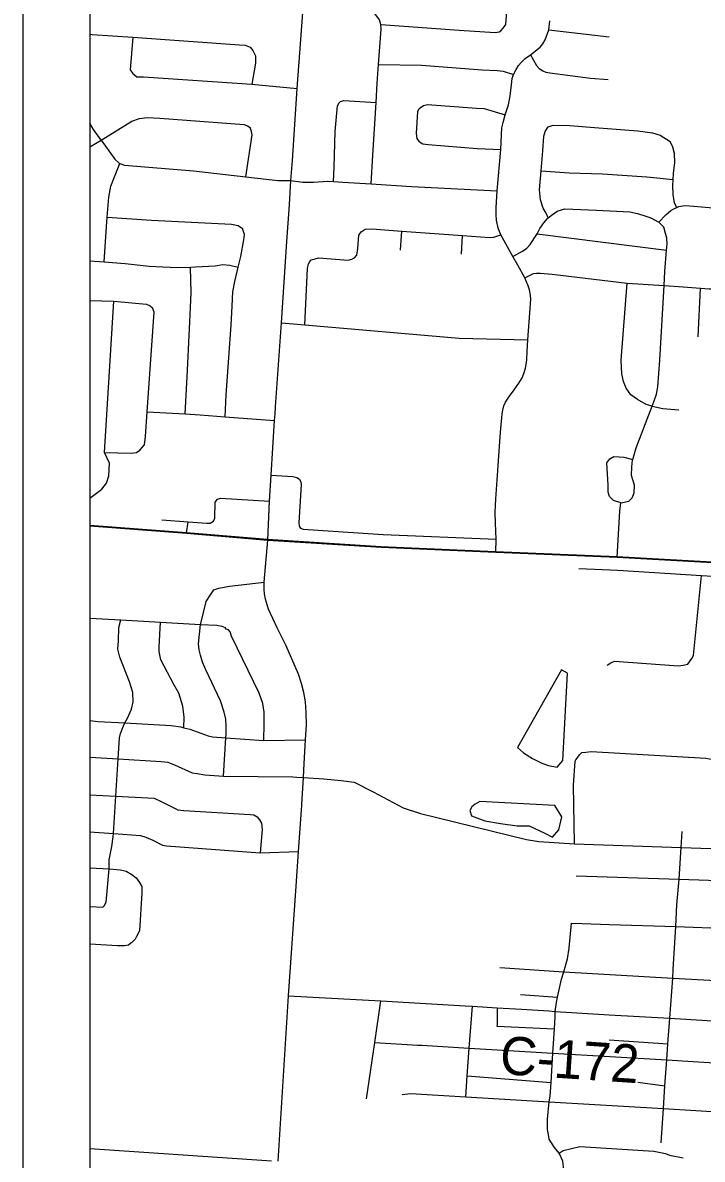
# Model space of a CAD drawing. Extents: x 0 to 34, y 0 to 22.
# Drawn here: x 2 to 3.011, y 15.572 to 17.262 of the extents above; entities that cross this region are included whole.
import ezdxf

# ---------------------------------------------------------------- set-up
doc = ezdxf.new("R2010")
doc.units = 0
for name, color, linetype in [('GM_X_City_Street', 7, 'Continuous'), ('GM_X_Corporation', 7, 'Continuous'), ('GM_X_County_Road', 7, 'Continuous'), ('GM_X_County_Road_Text', 7, 'Continuous'), ('GM_X_Minor_Lake', 7, 'Continuous'), ('GM_X_Township_Road', 7, 'Continuous'), ('SH_Data', 7, 'Continuous')]:
    doc.layers.add(name, color=color, linetype=linetype)

msp = doc.modelspace()

# ---------------------------------------------------------------- linework, layer by layer
at = {"layer": 'GM_X_City_Street'}
for p, q in [((2.7828, 17.2515), (2.8725, 17.2408)), ((2.5622, 16.9236), (2.5639, 16.9521)), ((2.6529, 16.9176), (2.6544, 16.9455)), ((2.7655, 16.9481), (2.9578, 16.9236)), ((3.0049, 16.795), (3.0084, 16.8673)), ((2.2071, 16.5224), (2.2462, 16.5198))]:
    msp.add_line(p, q, dxfattribs=at)
for points in [[(2.3754, 16.6801), (2.3762, 16.6907), (2.3851, 16.8158), (2.393, 16.9367), (2.3967, 16.9913), (2.3987, 17.0273), (2.4012, 17.0569), (2.4084, 17.1642), (2.416, 17.2704), (2.4254, 17.4108), (2.4323, 17.5151), (2.4397, 17.6214), (2.4448, 17.7051), (2.4589, 17.9206), (2.4607, 17.957), (2.4706, 18.1283), (2.4796, 18.2726), (2.4824, 18.3215)], [(2.7114, 17.2497), (2.7145, 17.2538), (2.7189, 17.2593), (2.7221, 17.3047), (2.7236, 17.3198), (2.724, 17.3301), (2.7255, 17.3353), (2.7272, 17.3394), (2.7299, 17.344), (2.7349, 17.349), (2.7398, 17.3524), (2.7463, 17.3546), (2.7525, 17.3548), (2.7901, 17.3519)], [(2.5183, 17.0222), (2.5209, 17.0652), (2.5257, 17.1435), (2.5274, 17.1719), (2.5294, 17.1998), (2.5332, 17.2524), (2.5329, 17.2593), (2.5307, 17.2662), (2.5208, 17.2798)], [(2.5329, 17.2593), (2.6491, 17.251), (2.7027, 17.2476), (2.7087, 17.2482), (2.7114, 17.2497)], [(2.7036, 16.4747), (2.7044, 16.4939), (2.7034, 16.5177), (2.703, 16.5338), (2.7037, 16.5537), (2.7057, 16.5816), (2.7087, 16.625), (2.7109, 16.6528), (2.7128, 16.6742), (2.7132, 16.6804), (2.7141, 16.6856), (2.7156, 16.692), (2.7184, 16.6975), (2.7242, 16.7068), (2.731, 16.7161), (2.7381, 16.7259), (2.7428, 16.7339), (2.7454, 16.7403), (2.748, 16.7483), (2.7493, 16.7566), (2.7498, 16.7613), (2.7505, 16.7728), (2.7514, 16.7902), (2.755, 16.8368), (2.7556, 16.8448), (2.7557, 16.8502), (2.7555, 16.8568), (2.754, 16.8649), (2.7519, 16.8708), (2.7471, 16.8824), (2.7365, 16.9013), (2.7293, 16.9141), (2.7112, 16.9465), (2.7071, 16.9562), (2.7048, 16.9681), (2.7042, 16.9763), (2.7045, 16.9868), (2.7057, 17.012), (2.7111, 17.0733), (2.7127, 17.1056), (2.7145, 17.1134), (2.7179, 17.1252), (2.7227, 17.1398), (2.7253, 17.153), (2.7271, 17.1694), (2.7283, 17.179), (2.7299, 17.185), (2.7339, 17.1924), (2.7377, 17.1982), (2.7417, 17.203), (2.7475, 17.2088), (2.7552, 17.2141), (2.77, 17.2254), (2.7737, 17.2304), (2.777, 17.2365), (2.7828, 17.2515), (2.7842, 17.2647)], [(2.1, 17.2448), (2.1032, 17.2446), (2.1638, 17.2404), (2.3227, 17.2292), (2.331, 17.2288), (2.3382, 17.2258), (2.3424, 17.2208), (2.3462, 17.2128), (2.3461, 17.2018), (2.341, 17.1708)], [(2.1638, 17.2404), (2.16, 17.1919), (2.1635, 17.1869), (2.1699, 17.1816), (2.1798, 17.1816), (2.341, 17.1708), (2.4084, 17.1642)], [(2.7552, 17.2141), (2.7642, 17.1983), (2.7682, 17.194), (2.7735, 17.1904), (2.7784, 17.1883), (2.7843, 17.1873), (2.8446, 17.1796), (2.8708, 17.1773)], [(2.5294, 17.1998), (2.5934, 17.1988), (2.6835, 17.1918), (2.7057, 17.1908), (2.7145, 17.19), (2.7299, 17.185)], [(2.4621, 17.0258), (2.4633, 17.0471), (2.4648, 17.1003), (2.4684, 17.1382), (2.4708, 17.1428), (2.4727, 17.145)], [(2.4727, 17.145), (2.4777, 17.1465), (2.4856, 17.146), (2.5257, 17.1435)], [(2.5898, 17.1346), (2.5962, 17.139), (2.6024, 17.1402), (2.6749, 17.135), (2.6867, 17.1342), (2.7179, 17.1252)], [(2.5904, 17.0846), (2.5868, 17.0898), (2.5856, 17.0972), (2.588, 17.1298), (2.5898, 17.1346)], [(2.1, 17.0775), (2.1168, 17.0874), (2.1625, 17.1155), (2.1739, 17.1193), (2.1853, 17.1212), (2.2042, 17.1199), (2.3295, 17.1104), (2.3344, 17.1084), (2.3386, 17.1062)], [(2.1168, 17.0874), (2.1051, 17.1032), (2.1, 17.1128)], [(2.3318, 17.0328), (2.3412, 17.0951), (2.3401, 17.1001), (2.3386, 17.1062)], [(2.7806, 17.1058), (2.7818, 17.1073), (2.789, 17.1095), (2.8137, 17.1092), (2.8505, 17.1061), (2.9151, 17.1012), (2.9371, 17.098), (2.9485, 17.0948), (2.9632, 17.0851)], [(2.7818, 16.9718), (2.7789, 16.9785), (2.7744, 16.9861), (2.7703, 16.9987), (2.769, 17.0132), (2.7713, 17.0417), (2.7738, 17.0716), (2.7751, 17.0933), (2.7771, 17.1001), (2.7806, 17.1058)], [(2.1168, 17.0874), (2.1369, 17.0589), (2.1433, 17.0531), (2.1444, 17.0527), (2.1512, 17.05), (2.2541, 17.0415), (2.3318, 17.0328), (2.3797, 17.0275)], [(2.5904, 17.0846), (2.5954, 17.0816), (2.6034, 17.0806), (2.6762, 17.075), (2.7111, 17.0733)], [(2.973, 16.9869), (2.9698, 16.9934), (2.9677, 17.0064), (2.9671, 17.0197), (2.9675, 17.0287), (2.968, 17.0379), (2.9701, 17.0539), (2.9695, 17.0676), (2.9669, 17.0767), (2.9632, 17.0851)], [(2.1214, 16.9062), (2.1247, 16.9585), (2.1258, 16.973), (2.1279, 17.0025), (2.131, 17.0188), (2.1375, 17.0351), (2.1444, 17.0527)], [(2.7713, 17.0417), (2.8129, 17.0385), (2.8623, 17.0372), (2.9284, 17.033), (2.9675, 17.0287)], [(2.3797, 17.0275), (2.3837, 17.0272), (2.3987, 17.0273), (2.4166, 17.025), (2.4325, 17.0247), (2.4538, 17.0263), (2.4621, 17.0258), (2.4762, 17.0248), (2.5183, 17.0222), (2.5784, 17.0183), (2.7057, 17.012)], [(2.9463, 16.9652), (2.9567, 16.9761), (2.9644, 16.9825), (2.9697, 16.9855), (2.973, 16.9869), (2.9762, 16.9884), (2.985, 16.9899), (2.9986, 16.9889), (3.0211, 16.9872), (3.0845, 16.9822), (3.1057, 16.9805), (3.1133, 16.9808), (3.1154, 16.9816), (3.1191, 16.983), (3.1286, 16.989), (3.1425, 17.0022), (3.1711, 17.0347)], [(2.1258, 16.973), (2.1916, 16.9685), (2.3108, 16.9623), (2.3203, 16.9604), (2.3267, 16.9558)], [(2.7293, 16.9141), (2.7437, 16.9222), (2.7497, 16.9265), (2.755, 16.9322), (2.7655, 16.9481), (2.7695, 16.9561), (2.7753, 16.9641), (2.7807, 16.9708), (2.7818, 16.9718), (2.788, 16.9768), (2.7952, 16.9817), (2.8063, 16.985), (2.8534, 16.9833), (2.9032, 16.9805), (2.9145, 16.9781), (2.9255, 16.9749), (2.9346, 16.9718), (2.9463, 16.9652)], [(2.3011, 16.6758), (2.3028, 16.7083), (2.3099, 16.812), (2.3115, 16.8404), (2.3127, 16.8617), (2.3155, 16.8773), (2.3205, 16.8982), (2.3243, 16.9144), (2.3289, 16.9391), (2.3297, 16.9471), (2.3267, 16.9558)], [(2.4289, 16.9092), (2.435, 16.911), (2.44, 16.9125), (2.484, 16.9088), (2.4898, 16.9102), (2.4936, 16.9124), (2.4971, 16.9162), (2.4987, 16.926), (2.4998, 16.9462), (2.5033, 16.951), (2.5094, 16.9548), (2.5193, 16.9554), (2.5639, 16.9521), (2.6544, 16.9455), (2.6946, 16.9426), (2.7008, 16.9431), (2.7112, 16.9465)], [(2.8842, 16.467), (2.8881, 16.5354), (2.89, 16.5477), (2.9015, 16.5503), (2.9067, 16.5552), (2.9094, 16.5626), (2.91, 16.5741), (2.9054, 16.5886), (2.9063, 16.6015), (2.9072, 16.6114), (2.9076, 16.6126), (2.9127, 16.6295), (2.9363, 16.6916), (2.9393, 16.6996), (2.9428, 16.7094), (2.9448, 16.7204), (2.9479, 16.7603), (2.9542, 16.8712), (2.9554, 16.8921), (2.9578, 16.9236), (2.9585, 16.9327), (2.9582, 16.9422), (2.9564, 16.9487), (2.9535, 16.9579), (2.9463, 16.9652)], [(2.1, 16.908), (2.1214, 16.9062), (2.1523, 16.9037), (2.188, 16.9001), (2.2085, 16.8989), (2.2301, 16.8977), (2.2498, 16.8985), (2.2571, 16.8987), (2.2863, 16.9005), (2.2977, 16.9024), (2.3083, 16.9016), (2.3205, 16.8982)], [(2.4198, 16.8127), (2.4238, 16.8964), (2.425, 16.9036), (2.427, 16.9066), (2.4289, 16.9092)], [(2.2415, 16.6802), (2.2448, 16.7355), (2.248, 16.8069), (2.2505, 16.86), (2.2498, 16.8985)], [(2.7471, 16.8824), (2.7557, 16.8872), (2.7599, 16.8889), (2.7642, 16.8895), (2.77, 16.8893), (2.7875, 16.8881), (2.899, 16.8748), (2.9542, 16.8712), (2.9825, 16.8694), (3.0084, 16.8673), (3.0213, 16.8663), (3.0277, 16.8662), (3.0395, 16.868), (3.0586, 16.8727), (3.0666, 16.873), (3.0784, 16.8733), (3.1178, 16.8704), (3.1711, 16.8665)], [(2.9363, 16.6916), (2.9275, 16.6944), (2.9146, 16.7014), (2.9048, 16.7083), (2.8977, 16.7183), (2.8936, 16.7282), (2.8915, 16.7396), (2.8902, 16.7602), (2.899, 16.8748)], [(2.1, 16.8487), (2.1356, 16.848), (2.184, 16.8432), (2.1897, 16.8409), (2.1931, 16.8378)], [(2.1, 16.5547), (2.1175, 16.568), (2.1246, 16.5773), (2.1283, 16.5883), (2.1293, 16.6071), (2.1218, 16.6229), (2.1356, 16.848)], [(2.1218, 16.6229), (2.1612, 16.6219), (2.1692, 16.6226), (2.1742, 16.6264), (2.181, 16.6343), (2.1826, 16.6465), (2.1852, 16.6835), (2.1957, 16.8317), (2.1931, 16.8378)], [(2.3851, 16.8158), (2.4198, 16.8127), (2.6492, 16.793), (2.7514, 16.7902)], [(2.1852, 16.6835), (2.2415, 16.6802), (2.2639, 16.6788), (2.3011, 16.6758), (2.3747, 16.6703)], [(2.9363, 16.6916), (2.9525, 16.688), (2.976, 16.6862)], [(2.3644, 16.4926), (2.3672, 16.5502), (2.3696, 16.589), (2.3747, 16.6703), (2.3754, 16.6801)], [(2.89, 16.5477), (2.8791, 16.5514), (2.8731, 16.5572), (2.8711, 16.564), (2.8711, 16.5743), (2.8691, 16.6076), (2.8734, 16.6133), (2.8795, 16.617), (2.8875, 16.6165), (2.8943, 16.6157), (2.9076, 16.6126)], [(2.3696, 16.589), (2.402, 16.5872), (2.4078, 16.5857), (2.4117, 16.5832), (2.4138, 16.5789), (2.4142, 16.5752), (2.4106, 16.5184), (2.4114, 16.513), (2.4133, 16.5101), (2.4173, 16.5086), (2.5362, 16.5008), (2.7044, 16.4939)], [(2.2437, 16.5027), (2.2462, 16.5198), (2.2738, 16.5177), (2.2786, 16.5179), (2.2836, 16.5206), (2.2857, 16.5251), (2.2865, 16.5491), (2.2899, 16.5535), (2.2941, 16.5551), (2.3672, 16.5502)], [(2.4151, 16.0995), (2.4176, 16.1392), (2.4189, 16.1602), (2.4207, 16.1954), (2.422, 16.2177), (2.4219, 16.2362), (2.4206, 16.2521), (2.4181, 16.2658), (2.4149, 16.279), (2.4104, 16.2929), (2.3917, 16.3353), (2.3787, 16.3619), (2.3657, 16.3897), (2.3612, 16.4045), (2.3596, 16.4127), (2.3591, 16.4196), (2.3594, 16.4297), (2.3644, 16.4926)], [(2.8272, 16.4501), (2.8851, 16.4478), (3.0099, 16.44), (3.0775, 16.4361), (3.1074, 16.4346), (3.1381, 16.433), (3.1874, 16.4301), (3.2697, 16.4245), (3.406, 16.4147), (3.4454, 16.4112)], [(2.2989, 16.1413), (2.3022, 16.1984), (2.3026, 16.2039), (2.3028, 16.2161), (2.3023, 16.226), (2.2996, 16.2366), (2.2944, 16.2532), (2.2723, 16.2996), (2.2673, 16.311), (2.2645, 16.3216), (2.2626, 16.3291), (2.2613, 16.3382), (2.2646, 16.3672), (2.2648, 16.3687), (2.2728, 16.401), (2.2791, 16.4109), (2.2843, 16.4186), (2.2919, 16.421), (2.3077, 16.4238), (2.3594, 16.4297)], [(2.9894, 16.308), (2.9952, 16.3166), (2.998, 16.3211), (3.0099, 16.44)], [(2.1, 16.3764), (2.1458, 16.3739), (2.2048, 16.3706), (2.2646, 16.3672), (2.2887, 16.3659), (2.2963, 16.3644), (2.3012, 16.3626)], [(2.1286, 16.0035), (2.1285, 16.0168), (2.1328, 16.0369), (2.1345, 16.051), (2.1349, 16.0561), (2.1384, 16.1116), (2.1419, 16.1671), (2.1439, 16.1984), (2.1453, 16.2049), (2.1498, 16.2163), (2.1521, 16.2205), (2.1561, 16.2277), (2.162, 16.2411), (2.1641, 16.2518), (2.1636, 16.2658), (2.1589, 16.2817), (2.1445, 16.3183), (2.1417, 16.3301), (2.1427, 16.3426), (2.1432, 16.3624), (2.1458, 16.3739)], [(2.2397, 16.2135), (2.2402, 16.2294), (2.2381, 16.2454), (2.2322, 16.2647), (2.2249, 16.2779), (2.2055, 16.3145), (2.2031, 16.3266), (2.203, 16.3338), (2.2048, 16.3706)], [(2.3588, 16.1943), (2.3592, 16.2194), (2.359, 16.2365), (2.357, 16.2493), (2.3519, 16.2648), (2.3108, 16.3498), (2.3085, 16.3562), (2.3062, 16.3592), (2.3027, 16.36), (2.3012, 16.3626)], [(2.8692, 16.3064), (2.8749, 16.3101), (2.8803, 16.3126), (2.9757, 16.3057), (2.9825, 16.3063), (2.9894, 16.308)], [(2.1, 16.2243), (2.1118, 16.2227), (2.1521, 16.2205), (2.2206, 16.2167), (2.235, 16.2146), (2.2397, 16.2135), (2.2487, 16.2113), (2.265, 16.2054), (2.2757, 16.2014), (2.2822, 16.1999), (2.3022, 16.1984), (2.3588, 16.1943), (2.4207, 16.1954)], [(2.8281, 16.1733), (2.8316, 16.1766), (2.8376, 16.1773), (2.8456, 16.1779), (3.0163, 16.1681), (3.0273, 16.1664), (3.039, 16.1635), (3.0594, 16.1638), (3.0724, 16.1673), (3.0877, 16.175), (3.0985, 16.1842), (3.1077, 16.1901), (3.1233, 16.1913), (3.1419, 16.1912), (3.1426, 16.1912), (3.1446, 16.1911), (3.1515, 16.1907)], [(2.1, 16.1695), (2.1419, 16.1671), (2.206, 16.1634), (2.2158, 16.1621), (2.2256, 16.1584), (2.2522, 16.1465), (2.2594, 16.1456), (2.2711, 16.1434), (2.2989, 16.1413), (2.402, 16.1403), (2.4079, 16.1399)], [(2.8209, 16.0408), (2.8192, 16.1279), (2.8218, 16.1639), (2.8226, 16.1658), (2.8246, 16.168), (2.8281, 16.1733)], [(2.4079, 16.1399), (2.4176, 16.1392), (2.4477, 16.1372), (2.4735, 16.1349), (2.4933, 16.1324), (2.5211, 16.118), (2.566, 16.0942), (2.5916, 16.0857), (2.7496, 16.0472), (2.768, 16.0441), (2.8209, 16.0408)], [(2.1, 16.1134), (2.1384, 16.1116), (2.1862, 16.1093), (2.1953, 16.1086), (2.2059, 16.1038), (2.2307, 16.0915), (2.2398, 16.0901), (2.3383, 16.0844), (2.344, 16.0837), (2.3486, 16.0811), (2.3524, 16.0766), (2.3552, 16.0713), (2.356, 16.0622), (2.353, 16.0275)], [(2.3799, 15.5688), (2.3956, 15.8148), (2.4066, 15.9776), (2.4102, 16.0293), (2.415, 16.0976), (2.4151, 16.0995)], [(2.1, 16.0585), (2.1349, 16.0561), (2.175, 16.0533), (2.183, 16.0508), (2.1937, 16.0463), (2.2078, 16.0389), (2.2139, 16.0378), (2.353, 16.0275), (2.4102, 16.0293)], [(2.9733, 15.95), (2.9766, 15.988), (2.9795, 16.0354), (2.981, 16.0589)], [(2.8209, 16.0408), (2.9795, 16.0354), (3.1417, 16.0298)], [(2.1, 16.005), (2.1286, 16.0035), (2.1347, 16.0032), (2.1457, 16.0022), (2.154, 16), (2.1624, 15.9951), (2.1689, 15.9903), (2.1735, 15.9831), (2.1774, 15.9771), (2.1771, 15.968), (2.1736, 15.9114), (2.1695, 15.903), (2.1673, 15.8988), (2.1628, 15.8945)], [(2.1, 15.9477), (2.119, 15.9464), (2.1213, 15.9487), (2.1242, 15.9541), (2.1286, 16.0035)], [(2.8235, 15.9931), (2.9766, 15.988), (3.0492, 15.9858), (3.0966, 15.9839), (3.1159, 15.9886), (3.1391, 15.9904)], [(2.1, 15.892), (2.1412, 15.8894), (2.1515, 15.8895), (2.1575, 15.8907), (2.1613, 15.8938), (2.1628, 15.8945)], [(2.5112, 15.6613), (2.5237, 15.7451), (2.5328, 15.8071)], [(2.7548, 15.2621), (2.761, 15.2846), (2.7651, 15.2972), (2.7718, 15.3086), (2.7845, 15.3283), (2.7879, 15.3384), (2.7892, 15.3501), (2.7914, 15.3638), (2.7977, 15.4379), (2.7984, 15.4602), (2.804, 15.543), (2.8049, 15.5558), (2.8035, 15.569), (2.7979, 15.5809), (2.791, 15.5893), (2.7832, 15.6015), (2.782, 15.6085)], [(2.7979, 15.5809), (2.8042, 15.5846), (2.8289, 15.5905), (2.9387, 15.5839), (2.9563, 15.5801), (2.9624, 15.5777), (2.9823, 15.5739)]]:
    msp.add_lwpolyline(points, dxfattribs=at)
at = {"layer": 'GM_X_Corporation'}
msp.add_lwpolyline([(2.1, 20.9), (2.1, 14.1), (6.2395, 14.1)], dxfattribs=at)
at = {"layer": 'GM_X_County_Road'}
msp.add_line((2.1, 15.5875), (2.3699, 15.5694), dxfattribs=at)
for points in [[(2.1, 20.9), (2.1, 16.5143), (2.2435, 16.5033), (2.3641, 16.4932), (2.5328, 16.4826), (2.7034, 16.4752), (2.884, 16.4676), (3.0788, 16.4569)], [(2.1, 16.5138), (2.2437, 16.5027), (2.3644, 16.4926), (2.533, 16.4821), (2.7036, 16.4747), (2.8842, 16.467), (3.079, 16.4564), (3.1587, 16.4501), (3.1869, 16.4491), (3.4067, 16.4347), (3.6175, 16.4183), (3.6542, 16.4148)], [(2.3956, 15.8148), (2.5328, 15.8071), (2.6584, 15.7997), (2.6692, 15.7992), (2.706, 15.7967)], [(2.706, 15.7967), (2.7419, 15.7949), (2.7826, 15.7922)], [(2.7826, 15.7922), (2.7921, 15.7915), (2.8726, 15.7865), (2.9627, 15.7816), (3.1368, 15.7707), (3.2073, 15.7668), (3.2598, 15.7632), (3.3228, 15.7599), (3.4447, 15.7525), (3.5351, 15.7469)]]:
    msp.add_lwpolyline(points, dxfattribs=at)
msp.add_lwpolyline([(2.1, 16.5143), (2.1, 14.1), (3.5033, 14.1), (3.5067, 14.1788), (3.5412, 14.6736), (3.5547, 14.8664), (3.6065, 15.7173), (3.6083, 15.7281), (3.6105, 15.7435), (3.6146, 15.8068), (3.6204, 15.8961), (3.634, 16.1053), (3.6418, 16.2257), (3.654, 16.4154), (3.6172, 16.4188), (3.4065, 16.4352), (3.1867, 16.4496), (3.1585, 16.4507), (3.0788, 16.4569), (2.884, 16.4676), (2.7034, 16.4752), (2.5328, 16.4826), (2.3641, 16.4932), (2.2435, 16.5033)], close=True, dxfattribs=at)
at = {"layer": 'GM_X_Minor_Lake'}
for points in [[(2.736, 16.184), (2.745, 16.176), (2.7582, 16.1679), (2.7722, 16.1609), (2.782, 16.1574), (2.7949, 16.155), (2.8037, 16.1648), (2.8103, 16.2945), (2.8016, 16.2996)], [(2.7362, 16.1838), (2.745, 16.176), (2.7582, 16.1679), (2.7722, 16.1609), (2.782, 16.1574), (2.7949, 16.155), (2.8037, 16.1648), (2.8103, 16.2945), (2.8016, 16.2996)], [(2.8016, 16.2996), (2.7362, 16.1838)], [(2.6798, 16.1037), (2.6733, 16.1), (2.6679, 16.0959), (2.6652, 16.0902), (2.6678, 16.0822), (2.6874, 16.0748), (2.7109, 16.0708), (2.7356, 16.0675), (2.7534, 16.0677), (2.7768, 16.0568), (2.7882, 16.0506), (2.7974, 16.0615), (2.8021, 16.0809), (2.7914, 16.0979)], [(2.7914, 16.0979), (2.6798, 16.1037)]]:
    msp.add_lwpolyline(points, dxfattribs=at)
at = {"layer": 'GM_X_Township_Road'}
for p, q in [((2.7406, 15.8168), (2.7957, 15.8127)), ((2.5938, 15.7411), (2.6639, 15.7369)), ((2.8724, 15.7495), (2.9599, 15.7432)), ((2.6612, 15.6956), (2.786, 15.686)), ((2.915, 15.6861), (2.9554, 15.6807))]:
    msp.add_line(p, q, dxfattribs=at)
for points in [[(2.9496, 15.5963), (2.953, 15.647), (2.9554, 15.6807), (2.9582, 15.7193), (2.9599, 15.7432), (2.9627, 15.7816), (2.967, 15.841), (2.9677, 15.8539), (2.9716, 15.9176), (2.9733, 15.95)], [(2.786, 15.686), (2.7887, 15.7295), (2.791, 15.7656), (2.7922, 15.7838), (2.7921, 15.7915), (2.7939, 15.8048), (2.7957, 15.8127), (2.8017, 15.8393), (2.8052, 15.8506), (2.8103, 15.8695), (2.813, 15.8858), (2.8166, 15.9227)], [(2.8166, 15.9227), (2.8322, 15.9221), (2.8731, 15.9208), (2.9716, 15.9176), (3.0492, 15.915), (3.1141, 15.9128), (3.1346, 15.9118), (3.1418, 15.9115), (3.1728, 15.915), (3.2063, 15.9194), (3.2155, 15.9196)], [(2.71, 15.8568), (2.8052, 15.8506), (2.967, 15.841), (3.1326, 15.8322), (3.2027, 15.829)], [(2.6591, 15.6647), (2.6612, 15.6956), (2.6639, 15.7369), (2.6692, 15.7992)], [(2.706, 15.7967), (2.7057, 15.7728), (2.7053, 15.7698), (2.791, 15.7656)], [(2.5237, 15.7451), (2.5878, 15.7414), (2.5938, 15.7411)], [(2.6639, 15.7369), (2.7887, 15.7295), (2.9582, 15.7193), (3.0914, 15.7113), (3.1325, 15.7086), (3.3183, 15.6979), (3.4403, 15.6907), (3.505, 15.6861), (3.5393, 15.684)], [(2.782, 15.6085), (2.7807, 15.6158), (2.7809, 15.6312), (2.7831, 15.6569), (2.7847, 15.6653), (2.786, 15.686)], [(2.5646, 15.6678), (2.5768, 15.6697), (2.6591, 15.6647), (2.7831, 15.6569), (2.953, 15.647), (3.0492, 15.641), (3.0818, 15.6394), (3.0965, 15.6387), (3.1094, 15.6378)]]:
    msp.add_lwpolyline(points, dxfattribs=at)
at = {"layer": 'SH_Data'}
for p, q in [((2, 21), (2, 14)), ((2.1, 20.9), (2.1, 14.1))]:
    msp.add_line(p, q, dxfattribs=at)

# ---------------------------------------------------------------- texts
at = {"layer": 'GM_X_County_Road_Text'}
msp.add_text('C-172', height=0.05682, rotation=356.152, dxfattribs=at).set_placement((2.7087, 15.6986))

doc.saveas('drawing.dxf')
